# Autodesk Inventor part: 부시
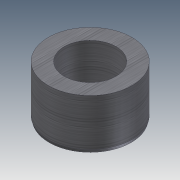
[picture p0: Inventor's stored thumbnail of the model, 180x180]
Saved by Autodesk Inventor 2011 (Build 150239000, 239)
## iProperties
Company: 한국ATC센터
Created: 2014-11
Part Number: 부시
Document SubType Name: Modeling
Designer: KYOUNG IL JANG
Density: 7.86 g/cm^3
Material: 강, 연강
Mass: 167.601 g
Surface Area: 70.0223 cm^2
Volume: 21.3233 cm^3
Author: KYOUNG IL JANG
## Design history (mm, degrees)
sketch "스케치1"
  geometry: C1 r 21 at (0, 0); C2 r 13 at (0, 0); 1 further point
  constraints: 2 centre point, 2 coincident
  dimensions: "d4" = 26 diameter of C2; "d5" = 42 diameter of C1
extrude "돌출1" new body sketch "스케치1" distance "d0" = 25; taper "d1" = 0 deg
chamfer "모따기1" distance "d6" = 1.5; stored, may be unused: second distance "d7" = 2, angle "d8" = 15 deg
node "솔리드1"
